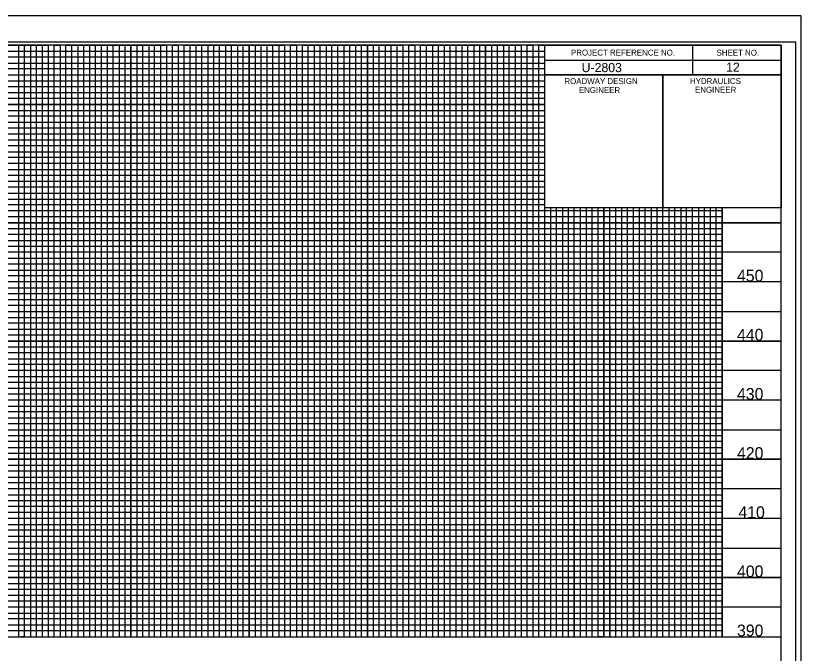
# Model space of a CAD drawing. Extents: x 571503 to 593215, y -77195 to -51828.
# Drawn here: x 583349 to 584014, y -76634 to -76095 of the extents above; entities that cross this region are included whole.
import ezdxf

# ---------------------------------------------------------------- set-up
doc = ezdxf.new("R2010")
doc.units = 0
for name, color, linetype in [('Exist Vertical Profile Vertical Axis Label', 7, 'Continuous'), ('Sheet Cutting Line CELL', 7, 'Continuous'), ('Sheet Data Field CELL', 7, 'Continuous'), ('Sheet DOT Grid CELL', 7, 'Continuous'), ('Sheet Layout Profile Border Port 1', 7, 'Continuous'), ('Sheet Plot Border Inside CELL', 7, 'Continuous'), ('Sheet Plot Border Outside CELL', 7, 'Continuous'), ('Sheet Profile CELL', 7, 'Continuous'), ('Sheet Profile Grid Major CELL', 7, 'Continuous'), ('Sheet Profile Grid Middle CELL', 7, 'Continuous'), ('Sheet Profile Grid Minor CELL', 7, 'Continuous')]:
    doc.layers.add(name, color=color, linetype=linetype)

msp = doc.modelspace()

# ---------------------------------------------------------------- linework, layer by layer
at = {"layer": 'Sheet Cutting Line CELL'}
msp.add_line((584013.98, -76095.23), (582329.98, -76095.23), dxfattribs=at)
at = {"layer": 'Sheet DOT Grid CELL'}
for p, q in [((583396.98, -76620.23), (583396.98, -76120.23)), ((583446.98, -76620.23), (583446.98, -76120.23)), ((583496.98, -76620.23), (583496.98, -76120.23)), ((583546.98, -76620.23), (583546.98, -76120.23)), ((583596.98, -76620.23), (583596.98, -76120.23)), ((583646.98, -76620.23), (583646.98, -76120.23)), ((583696.98, -76620.23), (583696.98, -76120.23)), ((583746.98, -76620.23), (583746.98, -76120.23)), ((583796.93, -76170.23), (582496.98, -76170.23)), ((583796.93, -76220.23), (582496.98, -76220.23)), ((583796.98, -76620.23), (583796.98, -76257.78)), ((583846.98, -76620.23), (583846.98, -76257.78)), ((583896.98, -76620.23), (583896.98, -76257.78)), ((583946.98, -76620.23), (583946.98, -76257.78)), ((583996.98, -76270.23), (582496.98, -76270.23)), ((583996.98, -76320.23), (582496.98, -76320.23)), ((583996.98, -76370.23), (582496.98, -76370.23)), ((583996.98, -76420.23), (582496.98, -76420.23)), ((583996.98, -76470.23), (582496.98, -76470.23)), ((583996.98, -76520.23), (582496.98, -76520.23)), ((583996.98, -76570.23), (582496.98, -76570.23))]:
    msp.add_line(p, q, dxfattribs=at)
at = {"layer": 'Sheet Layout Profile Border Port 1'}
msp.add_lwpolyline([(582546.98, -76120.23), (582546.98, -76620.23), (583946.98, -76620.23), (583946.98, -76257.78), (583796.93, -76257.78), (583796.93, -76120.23)], close=True, dxfattribs=at)
at = {"layer": 'Sheet Plot Border Inside CELL'}
msp.add_lwpolyline([(582342.98, -77172.78), (584009.48, -77172.78), (584009.48, -76117.68), (582342.98, -76117.68)], close=True, dxfattribs=at)
at = {"layer": 'Sheet Plot Border Outside CELL'}
msp.add_lwpolyline([(582329.98, -77195.23), (584013.98, -77195.23), (584013.98, -76095.23), (582329.98, -76095.23)], close=True, dxfattribs=at)
at = {"layer": 'Sheet Profile CELL'}
for p, q in [((583921.98, -76120.28), (583921.98, -76145.28)), ((583796.93, -76132.78), (583996.98, -76132.78)), ((583896.98, -76145.28), (583896.98, -76257.73)), ((582496.98, -76620.23), (583996.98, -76620.23))]:
    msp.add_line(p, q, dxfattribs=at)
for points in [[(583996.98, -76120.23), (582496.98, -76120.23), (582496.98, -77170.23), (583996.98, -77170.23)], [(583796.93, -76120.23), (583996.98, -76120.23), (583996.98, -76145.28), (583796.93, -76145.28)], [(583796.93, -76145.28), (583896.98, -76145.28), (583896.98, -76257.78), (583796.93, -76257.78)], [(583896.98, -76145.28), (583996.98, -76145.28), (583996.98, -76257.78), (583896.98, -76257.78)]]:
    msp.add_lwpolyline(points, close=True, dxfattribs=at)
at = {"layer": 'Sheet Profile Grid Major CELL'}
for points in [[(583346.98, -76620.23), (583396.98, -76620.23), (583396.98, -76120.23), (583446.98, -76120.23), (583446.98, -76620.23), (583496.98, -76620.23), (583496.98, -76120.23), (583546.98, -76120.23), (583546.98, -76620.23), (583596.98, -76620.23), (583596.98, -76120.23), (583646.98, -76120.23), (583646.98, -76620.23), (583696.98, -76620.23), (583696.98, -76120.23), (583746.98, -76120.23), (583746.98, -76620.23), (583796.98, -76620.23), (583796.98, -76120.23), (583823.28, -76120.23)], [(582496.98, -76170.23), (583796.98, -76170.23)], [(583796.98, -76220.23), (582496.98, -76220.23), (582496.98, -76270.23), (583996.98, -76270.23)], [(583846.98, -76257.78), (583846.98, -76620.23), (583896.98, -76620.23), (583896.98, -76620.23), (583896.98, -76257.78)], [(583946.98, -76257.78), (583946.98, -76620.23), (583996.98, -76620.23), (583996.98, -76270.23)], [(583996.98, -76320.23), (582496.98, -76320.23), (582496.98, -76370.23), (583996.98, -76370.23)], [(583996.98, -76420.23), (582496.98, -76420.23), (582496.98, -76470.23), (583996.98, -76470.23)], [(583996.98, -76520.23), (582496.98, -76520.23), (582496.98, -76520.23), (582496.98, -76570.23), (583996.98, -76570.23)]]:
    msp.add_lwpolyline(points, dxfattribs=at)
at = {"layer": 'Sheet Profile Grid Middle CELL'}
msp.add_line((582496.98, -76145.23), (583796.93, -76145.23), dxfattribs=at)
for points in [[(583321.98, -76120.23), (583371.98, -76120.23), (583371.98, -76620.23), (583421.98, -76620.23), (583421.98, -76120.23), (583471.98, -76120.23), (583471.98, -76620.23), (583521.98, -76620.23), (583521.98, -76120.23), (583571.98, -76120.23), (583571.98, -76620.23), (583621.98, -76620.23), (583621.98, -76120.23), (583671.98, -76120.23), (583671.98, -76620.23), (583721.98, -76620.23), (583721.98, -76120.23), (583771.98, -76120.23), (583771.98, -76620.23), (583821.98, -76620.23), (583821.98, -76257.78)], [(583796.98, -76195.23), (582496.98, -76195.23), (582496.98, -76245.23), (583796.98, -76245.23)], [(583821.98, -76357.43), (583821.98, -76620.23), (583871.98, -76620.23), (583871.98, -76257.78)], [(583871.98, -76357.43), (583871.98, -76620.23), (583921.98, -76620.23), (583921.98, -76257.78)], [(583996.98, -76295.23), (582496.98, -76295.23), (582496.98, -76345.23), (583821.98, -76345.23)], [(583821.98, -76345.23), (583996.98, -76345.23)], [(583996.98, -76395.23), (582496.98, -76395.23), (582496.98, -76445.23), (583996.98, -76445.23)], [(583996.98, -76495.23), (582496.98, -76495.23), (582496.98, -76545.23), (583996.98, -76545.23)], [(583996.98, -76595.23), (582496.98, -76595.23)]]:
    msp.add_lwpolyline(points, dxfattribs=at)
at = {"layer": 'Sheet Profile Grid Minor CELL'}
for p, q in [((582546.98, -76125.23), (583796.98, -76125.23)), ((583796.98, -76130.23), (582546.98, -76130.58)), ((582546.98, -76135.23), (583796.98, -76135.23)), ((583796.93, -76255.23), (582546.98, -76255.23)), ((583946.98, -76260.23), (582546.98, -76260.23)), ((583946.98, -76265.23), (582546.98, -76265.23)), ((582546.98, -76275.23), (583946.98, -76275.23)), ((583946.98, -76280.23), (582546.98, -76280.23)), ((582546.98, -76285.23), (583946.98, -76285.23)), ((583946.98, -76305.23), (582546.98, -76305.23)), ((582546.98, -76310.23), (583946.98, -76310.23)), ((583946.98, -76330.23), (582546.98, -76330.23)), ((582546.98, -76335.23), (583946.98, -76335.23)), ((583946.98, -76355.23), (582546.98, -76355.23)), ((582546.98, -76360.23), (583946.98, -76360.23)), ((583946.98, -76365.23), (582546.98, -76365.23)), ((582546.98, -76375.23), (583946.98, -76375.23)), ((583946.98, -76380.23), (582546.98, -76380.23)), ((582546.98, -76385.23), (583946.98, -76385.23)), ((583946.98, -76390.23), (582546.98, -76390.23)), ((582546.98, -76400.23), (583946.98, -76400.23)), ((583946.98, -76405.23), (582546.98, -76405.23)), ((582546.98, -76410.23), (583946.98, -76410.23)), ((583946.98, -76415.23), (582546.98, -76415.23)), ((582546.98, -76425.23), (583946.98, -76425.23)), ((583946.98, -76430.23), (582546.98, -76430.23)), ((582546.98, -76435.23), (583946.98, -76435.23)), ((583946.98, -76440.23), (582546.98, -76440.23)), ((582546.98, -76450.23), (583946.98, -76450.23)), ((583946.98, -76455.23), (582546.98, -76455.23)), ((582546.98, -76460.23), (583946.98, -76460.23)), ((583946.98, -76465.23), (582546.98, -76465.23)), ((582546.98, -76475.23), (583946.98, -76475.23)), ((583946.98, -76480.23), (582546.98, -76480.23)), ((582546.98, -76485.23), (583946.98, -76485.23)), ((583946.98, -76490.23), (582546.98, -76490.23)), ((582546.98, -76500.23), (583946.98, -76500.23)), ((583946.98, -76505.23), (582546.98, -76505.23)), ((583946.98, -76510.23), (582546.98, -76510.23)), ((583946.98, -76515.23), (582546.98, -76515.23)), ((582546.98, -76525.23), (583946.98, -76525.23)), ((583946.98, -76530.23), (582546.98, -76530.23)), ((582546.98, -76535.23), (583946.98, -76535.23)), ((583946.98, -76540.23), (582546.98, -76540.23)), ((582546.98, -76550.23), (583946.98, -76550.23)), ((583946.98, -76555.23), (582546.98, -76555.23)), ((582546.98, -76560.23), (583946.98, -76560.23)), ((583946.98, -76565.23), (582546.98, -76565.23)), ((582546.98, -76575.23), (583946.98, -76575.23)), ((583946.98, -76580.23), (582546.98, -76580.23)), ((582546.98, -76585.23), (583946.98, -76585.23)), ((583946.98, -76590.23), (582546.98, -76590.23)), ((582546.98, -76600.23), (583946.98, -76600.23)), ((583946.98, -76605.23), (582546.98, -76605.23)), ((582546.98, -76610.23), (583946.98, -76610.23))]:
    msp.add_line(p, q, dxfattribs=at)
for points in [[(583341.98, -76120.23), (583351.98, -76120.23), (583351.98, -76620.23), (583356.68, -76619.68), (583356.98, -76620.23), (583356.98, -76120.23), (583361.98, -76120.23), (583361.98, -76620.23), (583366.98, -76620.23), (583366.98, -76120.23), (583376.98, -76120.23), (583376.98, -76620.23), (583381.98, -76620.23)], [(583381.98, -76620.23), (583381.98, -76120.23), (583386.98, -76120.23), (583386.98, -76620.23), (583391.98, -76620.23), (583391.98, -76120.23), (583401.98, -76120.23), (583401.98, -76620.23), (583406.98, -76620.23), (583406.98, -76120.23), (583411.98, -76120.23), (583411.98, -76620.23), (583416.98, -76620.23), (583416.98, -76120.23), (583426.98, -76120.23), (583426.98, -76620.23), (583431.98, -76620.23), (583431.98, -76120.23), (583436.98, -76120.23), (583436.98, -76620.23), (583441.98, -76620.23), (583441.98, -76120.23), (583451.98, -76120.23), (583451.98, -76620.23), (583456.98, -76620.23), (583456.98, -76120.23), (583461.98, -76120.23), (583461.98, -76620.23), (583466.98, -76620.23), (583466.98, -76120.23), (583476.98, -76120.23), (583476.98, -76620.23), (583481.98, -76620.23), (583481.98, -76120.23), (583486.98, -76120.23), (583486.98, -76620.23), (583491.98, -76620.23), (583491.98, -76120.23), (583501.98, -76120.23), (583501.98, -76620.23), (583506.98, -76620.23), (583506.98, -76120.23), (583511.98, -76120.23), (583511.98, -76620.23), (583516.98, -76620.23), (583516.98, -76120.23), (583526.98, -76120.23), (583526.98, -76620.23), (583531.98, -76620.23), (583531.98, -76120.23), (583536.98, -76120.23), (583536.98, -76620.23), (583541.98, -76620.23), (583541.98, -76120.23), (583551.98, -76120.23), (583551.98, -76620.23), (583556.98, -76620.23), (583556.98, -76120.23), (583561.98, -76120.23), (583561.98, -76620.23), (583566.98, -76620.23), (583566.98, -76120.23), (583576.98, -76120.23), (583576.98, -76620.23), (583581.98, -76620.23), (583581.98, -76120.23), (583586.98, -76120.23), (583586.98, -76620.23), (583591.98, -76620.23), (583591.98, -76120.23), (583601.98, -76120.23), (583601.98, -76620.23), (583606.98, -76620.23), (583606.98, -76120.23), (583611.98, -76120.23), (583611.98, -76620.23), (583616.98, -76620.23), (583616.98, -76120.23), (583626.98, -76120.23), (583626.98, -76620.23), (583631.98, -76620.23), (583631.98, -76120.23), (583636.98, -76120.23), (583636.98, -76620.23), (583641.98, -76620.23), (583641.98, -76120.23), (583651.98, -76120.23), (583651.98, -76620.23), (583656.98, -76620.23), (583656.98, -76120.23), (583661.98, -76120.23), (583661.98, -76620.23), (583666.98, -76620.23), (583666.98, -76120.23), (583676.98, -76120.23), (583676.98, -76620.23), (583681.98, -76620.23), (583681.98, -76120.23), (583686.98, -76120.23), (583686.98, -76620.23)], [(583686.98, -76620.23), (583691.98, -76620.23), (583691.98, -76120.23), (583701.98, -76120.23), (583701.98, -76620.23), (583706.98, -76620.23), (583706.98, -76120.23), (583711.98, -76120.23), (583711.98, -76620.23), (583716.98, -76620.23), (583716.98, -76120.23), (583726.98, -76120.23), (583726.98, -76620.23), (583731.98, -76620.23), (583731.98, -76120.23), (583736.98, -76120.23), (583736.98, -76620.23), (583741.98, -76620.23), (583741.98, -76120.23), (583751.98, -76120.23), (583751.98, -76620.23), (583756.98, -76620.23), (583756.98, -76120.23), (583761.98, -76120.23), (583761.98, -76620.23), (583766.98, -76620.23), (583766.98, -76120.23), (583776.98, -76120.23), (583776.98, -76620.23), (583781.98, -76620.23), (583781.98, -76120.23), (583786.98, -76120.23), (583786.98, -76620.23), (583791.98, -76620.23), (583791.98, -76120.23), (583801.98, -76120.23)], [(583796.98, -76140.23), (582546.98, -76140.23), (582546.98, -76150.23), (583796.98, -76150.23)], [(583796.93, -76155.23), (582546.98, -76155.23), (582546.98, -76160.23), (583796.98, -76160.23)], [(583796.98, -76165.23), (582546.98, -76165.23), (582546.98, -76175.23), (583796.98, -76175.23)], [(583796.98, -76180.23), (582546.98, -76180.23), (582546.98, -76185.23), (583796.98, -76185.23)], [(583796.98, -76190.23), (582546.98, -76190.23), (582546.98, -76200.23), (583796.98, -76200.23)], [(583796.98, -76205.23), (582546.98, -76205.23), (582546.98, -76210.23), (583796.98, -76210.23)], [(583796.98, -76215.23), (582546.98, -76215.23), (582546.98, -76225.23), (583796.98, -76225.23)], [(583796.98, -76230.33), (582547.08, -76230.33), (582547.08, -76235.23), (583796.98, -76235.23)], [(583796.98, -76240.23), (582546.98, -76240.23), (582546.98, -76250.23), (583796.98, -76250.23)], [(583801.98, -76257.78), (583801.98, -76620.23), (583806.98, -76620.23), (583806.98, -76257.78)], [(583811.98, -76257.78), (583811.98, -76620.23), (583816.98, -76620.23), (583816.98, -76257.78)], [(583826.98, -76257.78), (583826.98, -76620.23), (583826.98, -76620.23), (583831.98, -76620.23), (583836.98, -76620.23), (583836.98, -76257.78)], [(583831.98, -76257.78), (583831.98, -76620.23)], [(583841.98, -76257.78), (583841.88, -76620.18), (583846.88, -76620.18), (583851.98, -76620.23), (583851.98, -76257.78)], [(583851.98, -76357.43), (583851.98, -76620.23), (583856.98, -76620.23), (583856.98, -76257.78)], [(583861.98, -76257.78), (583861.98, -76620.23), (583866.98, -76620.23), (583866.98, -76257.78)], [(583876.98, -76257.78), (583876.98, -76620.23), (583881.98, -76620.23), (583881.98, -76257.78)], [(583886.98, -76257.78), (583886.98, -76620.23), (583891.98, -76620.23), (583891.98, -76257.78)], [(583901.98, -76257.78), (583901.98, -76620.23), (583906.98, -76620.23), (583906.98, -76257.78)], [(583911.98, -76257.78), (583911.98, -76620.23), (583916.98, -76620.23), (583916.98, -76257.78)], [(583926.98, -76257.78), (583926.98, -76620.23), (583931.98, -76620.23), (583931.98, -76257.78)], [(583936.98, -76257.78), (583936.98, -76620.23), (583941.98, -76620.23), (583941.98, -76257.78)], [(583946.98, -76290.23), (582546.98, -76290.23), (582546.98, -76300.23), (583946.98, -76300.23)], [(583946.98, -76315.23), (582546.98, -76315.23), (582546.98, -76325.23), (583946.98, -76325.23)], [(583946.98, -76340.23), (582546.98, -76340.23), (582546.98, -76350.23), (583946.98, -76350.23)], [(583946.98, -76615.23), (582546.98, -76615.23)]]:
    msp.add_lwpolyline(points, dxfattribs=at)

# ---------------------------------------------------------------- texts
at = {"layer": 'Exist Vertical Profile Vertical Axis Label'}
for s, p in [('450', (583959.63, -76319.98)), ('440', (583959.63, -76369.98)), ('430', (583959.63, -76419.98)), ('420', (583959.63, -76469.98)), ('410', (583960.82, -76519.98)), ('400', (583959.63, -76569.98)), ('390', (583959.63, -76619.98))]:
    msp.add_text(s, height=10, dxfattribs=at).set_placement(p)
at = {"layer": 'Sheet Data Field CELL'}
for s, p in [('U-2803   ', (583828.25, -76142.92)), ('12 ', (583950.4, -76142.62))]:
    msp.add_text(s, height=7.75, dxfattribs=at).set_placement(p)
at = {"layer": 'Sheet Profile CELL'}
for s, height, p in [('PROJECT REFERENCE NO.', 5.0001, (583819.15, -76128.92)), ('SHEET NO.', 5, (583942.3, -76129.02)), ('ROADWAY DESIGN', 5.0001, (583813.6, -76153.02)), ('HYDRAULICS', 5, (583919.8, -76152.97)), ('ENGINEER', 5, (583825.85, -76160.62)), ('ENGINEER', 5, (583924.05, -76160.32))]:
    msp.add_text(s, height=height, dxfattribs=at).set_placement(p)

doc.saveas('drawing.dxf')
